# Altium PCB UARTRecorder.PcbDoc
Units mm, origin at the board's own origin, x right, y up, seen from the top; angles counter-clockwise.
Board outline 152.4 x 101.6 mm, 2 copper layers (Top Layer, Bottom Layer); 66 components, 53 nets, 258 pads, 164 vias.
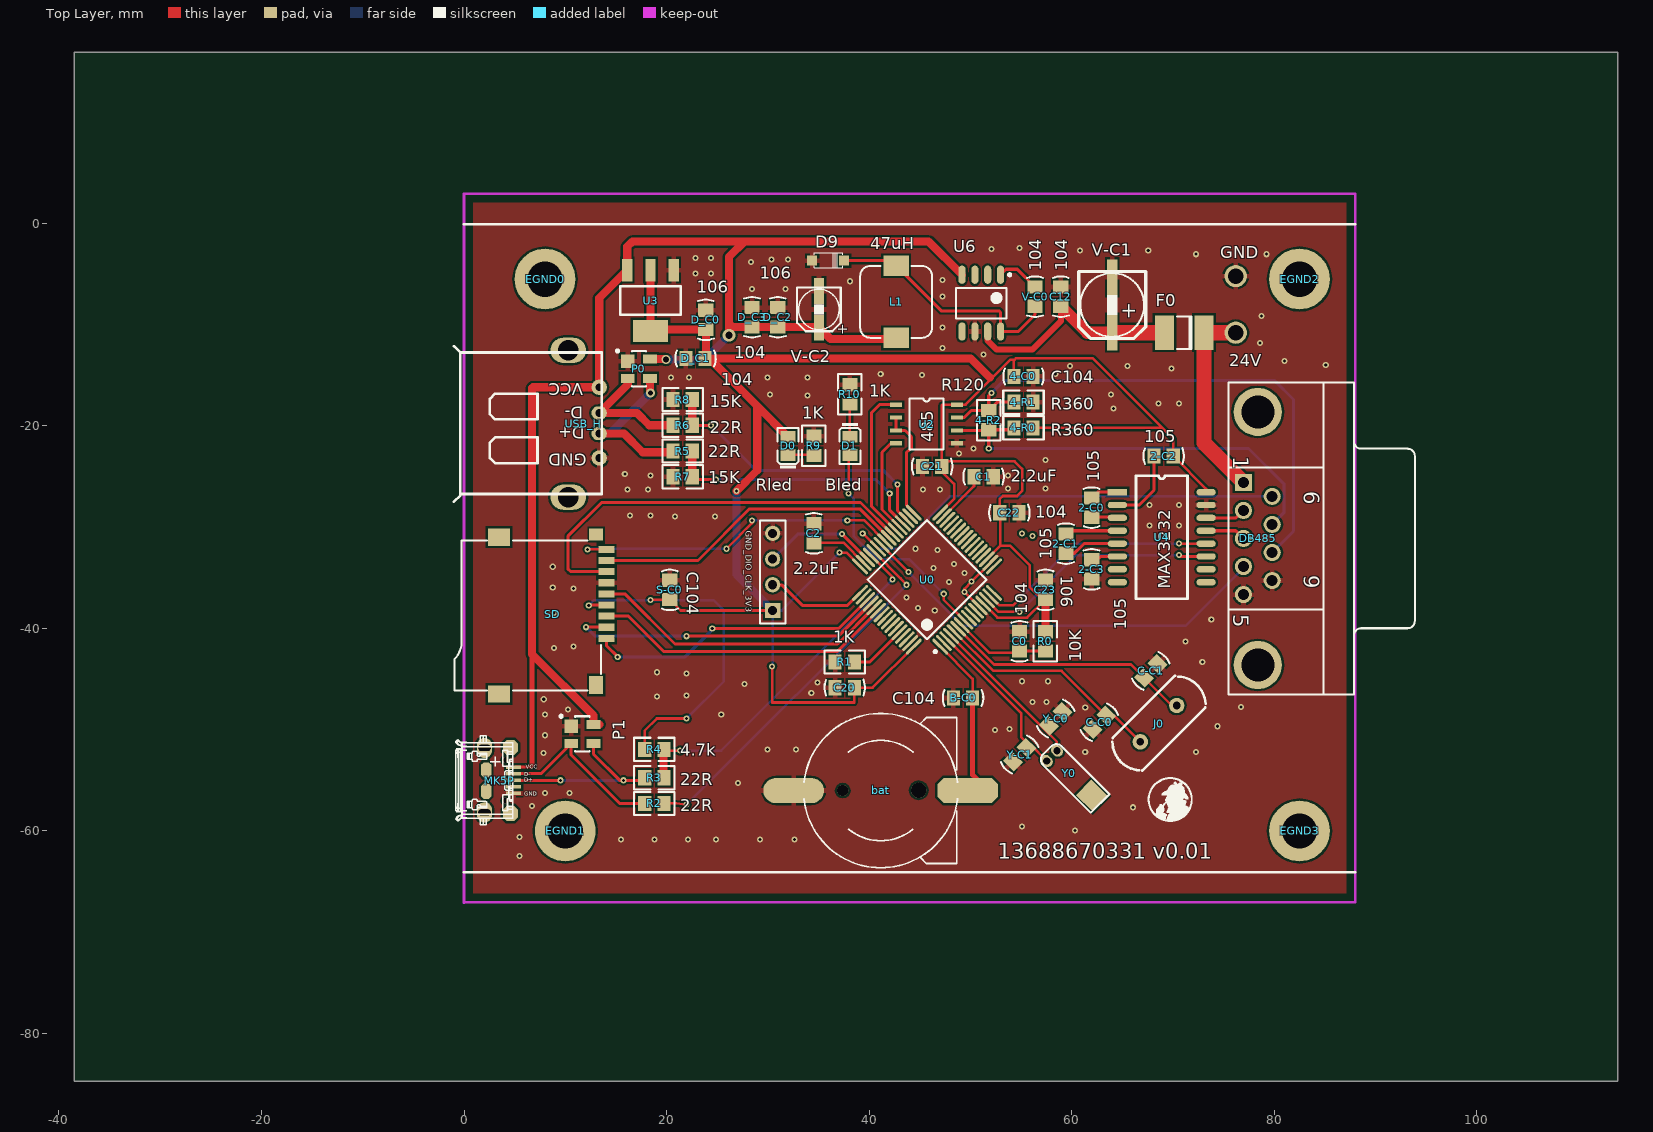
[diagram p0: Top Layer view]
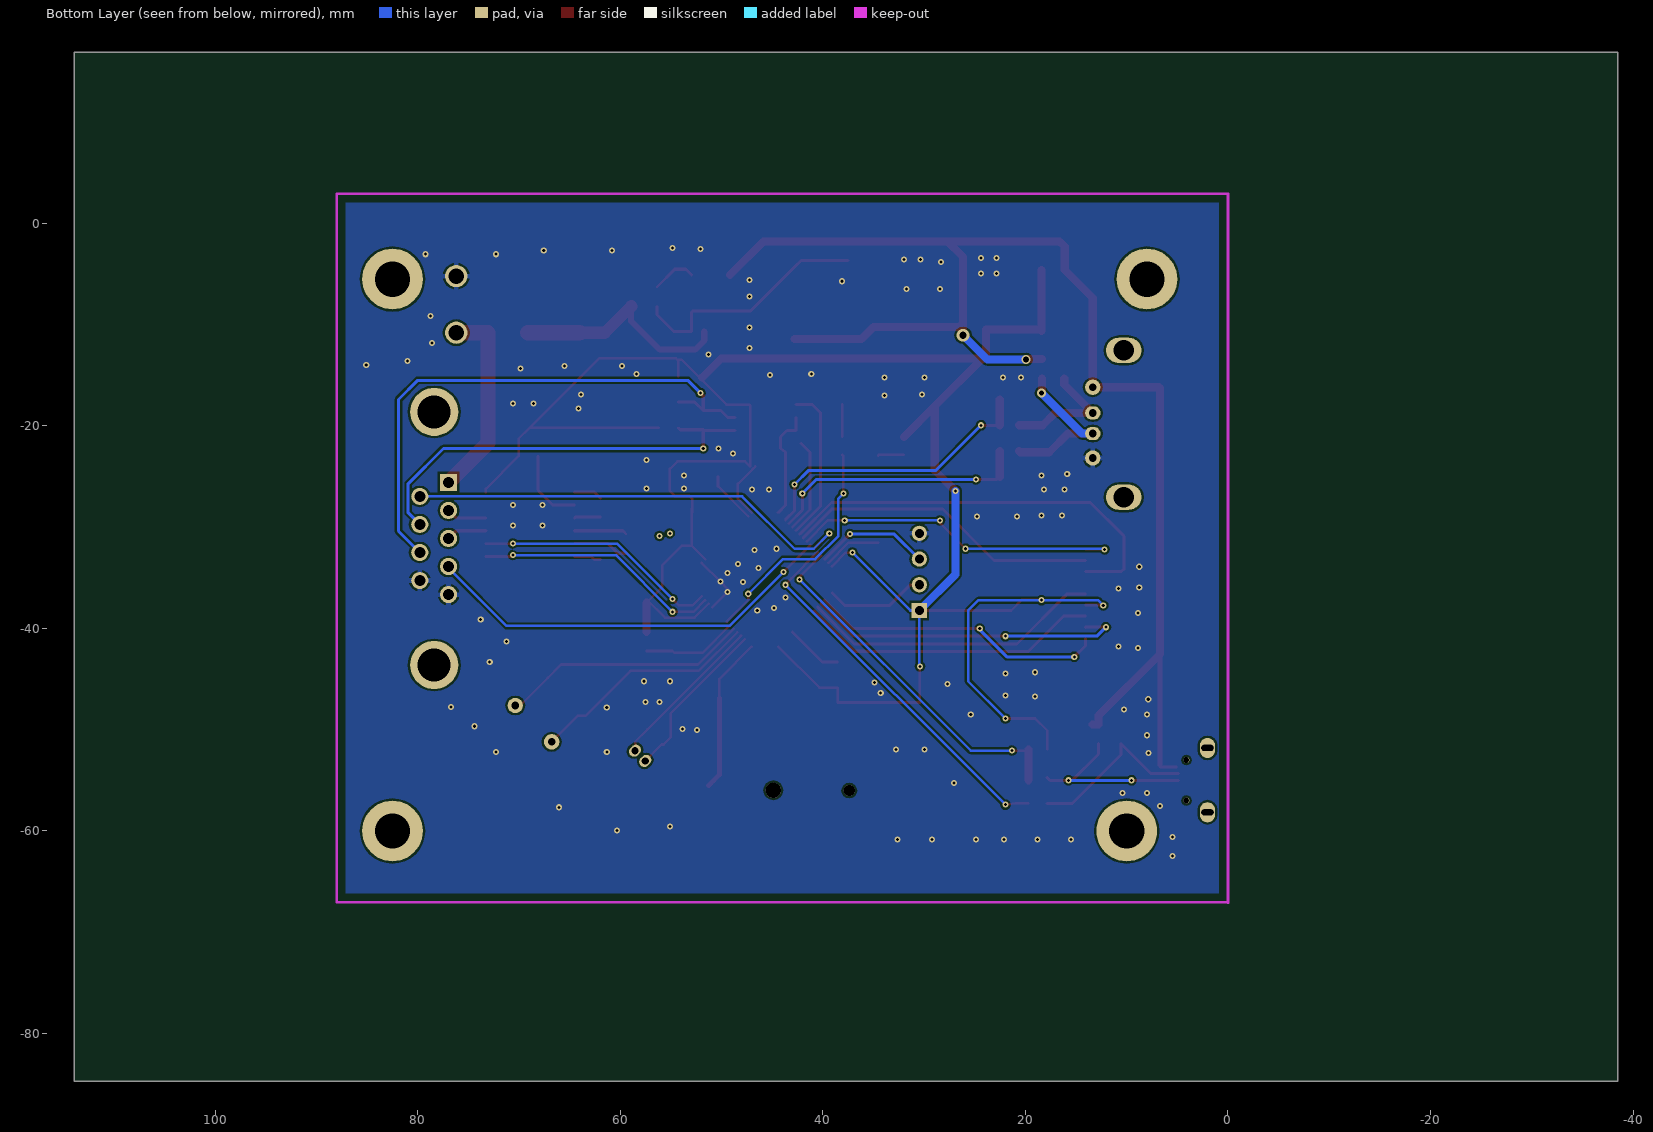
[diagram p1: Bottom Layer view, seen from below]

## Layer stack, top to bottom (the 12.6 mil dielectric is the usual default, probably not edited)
Top Layer: signal copper 0.0356
Dielectric: dielectric 0.32, FR-4, Dk 4.8
Bottom Layer: signal copper 0.0356

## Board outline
-38.481,-84.709 113.919,-84.709 113.919,16.891 -38.481,16.891

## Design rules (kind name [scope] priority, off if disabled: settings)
Clearance Clearance_keepout [(OnLayer('Keep-Out Layer'))] p1: gap=0.762
Clearance Clearance_ploy [inpoly] p2: gap=0.203
Clearance [All] p3: gap=0.152
ComponentClearance [All] p1: gap=0.127 collisioncheckmode=3 verticalgap=0.254 showdistances=FALSE
DiffPairsRouting DiffPair_DiffPairsRouting [InDifferentialPair ('VOUT2')] p1: maxlimit=0.254 minlimit=0.254 mostfreqgap=0.254 maxuncoupledlength=12.7
DiffPairsRouting [All] p2: maxlimit=0.254 minlimit=-0.044 mostfreqgap=0.254 toplayer_maxgap=-0.044 toplayer_prefgap=3.693 bottomlayer_maxgap=-0.044 bottomlayer_prefgap=2.348 maxuncoupledlength=12.7
HoleSize [All] p1: absolutevalues=TRUE maxlimit=5 minlimit=0.025 maxpercent=80.000 minpercent=20.000
HoleSize FabricationTestpoint [All] p2: absolutevalues=TRUE maxlimit=2.54 minlimit=0.025 maxpercent=80.000 minpercent=20.000
HoleSize FabricationTestPointUsage [All] p3: absolutevalues=TRUE maxlimit=2.54 minlimit=0.025 maxpercent=80.000 minpercent=20.000
Length [All] p1: maxlimit=152.4 minlimit=0
MatchedLengths DiffPair_MatchedLengths [InDifferentialPair ('VOUT2')] p1: tolerance=25.4 checknetsindiffpair=TRUE checkdiffpairvsdiffpair=TRUE checkothers=TRUE
MinimumSolderMaskSliver [All] p1: minsoldermaskwidth=0
MinimumSolderMaskSliver SilkToSolderMaskClearance [IsPad] p2: minsoldermaskwidth=0.254
NetAntennae AssemblyTestpoint [All] p1: netantennaetolerance=0
NetAntennae [All] p2: netantennaetolerance=0
NetAntennae AssemblyTestPointUsage [All] p3: netantennaetolerance=0
NetAntennae UnpouredPolygon [All] p4: netantennaetolerance=0
NetAntennae SilkToBoardRegionClearance [All] p5: netantennaetolerance=0
PlaneConnect [All] p1: planeconnectstyle=Direct reliefexpansion=0.508 reliefentries=4 reliefconductorwidth=0.254 reliefairgap=0.254
PolygonConnect PolygonConnect_VIA [ISVIA] p1: connectstyle=Direct reliefconductorwidth=0.254 reliefentries=4 polygonreliefangle="90 Angle"
PolygonConnect [All] p2: connectstyle=Relief reliefconductorwidth=0.508 reliefentries=4 polygonreliefangle="90 Angle"
RoutingVias [All] p1: holewidth=0.4 width=0.8 viastyle="Through Hole" minholewidth=0.3 minwidth=0.6 maxholewidth=1 maxwidth=2
SilkToSilkClearance [All] p1: silktosilkclearance=0
SilkscreenOverComponentPads [All] p1: minsilkscreentomaskgap=0.254
SolderMaskExpansion [All] p1: expansion=0.102
TestPointUsage [All] p1: valid=0 allowmultiple=FALSE
Testpoint [All] p1: side=15 testpointundercomponent=TRUE minsize=1.016 maxsize=2.54 preferedsize=1.524 minholesize=0 maxholesize=1.016 preferedholesize=0.813 testpointgrid=0.025 style=1023 order=0123456789
Width Width_VCC3.3 [InNet('G+3V3')] p1: maxlimit=2.54 minlimit=0.305 preferedwidth=0.305
Width DiffPair_Width [InDifferentialPair('VOUT2')] p2: maxlimit=0.254 minlimit=0.254 preferedwidth=0.254
Width [All] p3: maxlimit=2.54 minlimit=0.152 preferedwidth=0.203
16 further rules are at their usual default settings.

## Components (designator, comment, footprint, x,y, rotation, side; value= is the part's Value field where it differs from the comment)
2-C0 "105" C-RAD-0805 61.976,-28.067 r90 top
2-C1 "105" C-RAD-0805 59.436,-31.623 r90 top
2-C2 "105" C-RAD-0805 69.088,-22.987 r180 top
2-C3 "105" C-RAD-0805 61.976,-34.163 r90 top
4-C0 "C104" C-RAD-0805 55.245,-15.113 r180 top
4-R0 "R360" R2012-0805 55.245,-20.193 r180 top
4-R1 "R360" R2012-0805 55.245,-17.653 r180 top
4-R2 "R120" R2012-0805 51.816,-19.431 r90 top
24V "1孔" HOLEx1#1 76.2,-10.795 r0 top (schematic designator k0)
B-C0 "C104" C-RAD-0805 49.276,-46.863 r0 top
bat "Battery" BATM 41.148,-56.007 r90 top
C0 "104" C-RAD-0805 54.864,-41.275 r90 top
C1 "2.2uF" C-RAD-0805 51.308,-25.019 r0 top
C2 "2.2uF" C-RAD-0805 34.544,-30.607 r90 top
C12 "104" C-RAD-0805 58.928,-7.239 r90 top
C20 "104" C-RAD-0805 37.592,-45.847 r0 top
C21 "106" C-RAD-0805 46.228,-24.003 r0 top
C22 "104" C-RAD-0805 53.848,-28.575 r180 top
C23 "106" C-RAD-0805 57.404,-36.195 r270 top
C-C0 "22pF" C-RAD-0805 62.738,-49.276 r45 top
C-C1 "22pF" C-RAD-0805 67.818,-44.196 r225 top
D0 "Rled" 0805_LED_S1 32.004,-21.971 r90 top
D1 "Bled" 0805_LED_S1 38.1,-21.971 r270 top
D9 "S7" SOD123 36.576,-3.683 r0 top
D_C0 "106" C-RAD-0805 23.876,-9.525 r270 top
D_C1 "104" C-RAD-0805 22.86,-13.335 r0 top
D_C2 "106" C-RAD-0805 30.988,-9.271 r90 top
D_C3 "104" C-RAD-0805 28.448,-9.271 r90 top
DB485 "DB9母座" DB9-F 87.884,-31.115 r270 top locked
EGND0 "1孔" HOLEx1#2 5.588,-5.207 r90 top
EGND1 "1孔" HOLEx1#3 10.668,-59.436 r90 top
EGND2 "1孔" HOLEx1#4 81.788,6.096 r90 top
EGND3 "1孔" HOLEx1#5 76.708,-59.436 r90 top
F0 "Fuse 1" 1812 71.12,-10.795 r180 top
GND "1孔" HOLEx1#1 76.2,-5.207 r0 top (schematic designator k1)
GND_DIO_CLK_3V3 "Header 4" HDR1X4 30.48,-38.227 r90 top
J0 "25M" 晶振HC-49S 68.58,-49.403 r225 top
L1 "47uH" L-SMD-7 42.672,-7.747 r270 top
MK5P "五脚端子" USB-MICRO1 4.572,-54.991 r90 top
P0 "PRTR5V0U2X" SOT-143 17.272,-14.351 r270 top
P1 "PRTR5V0U2X" SOT-143 11.684,-50.419 r270 top
R0 "10K" R2012-0805 57.404,-41.275 r270 top
R1 "1K" R2012-0805 37.592,-43.307 r180 top
R2 "22R" R2012-0805 18.796,-57.277 r180 top
R3 "22R" R2012-0805 18.796,-54.737 r180 top
R4 "4.7k" R2012-0805 18.796,-51.943 r180 top
R5 "22R" R2012-0805 21.59,-22.479 r180 top
R6 "22R" R2012-0805 21.59,-19.939 r180 top
R7 "15K" R2012-0805 21.59,-25.019 r180 top
R8 "15K" R2012-0805 21.59,-17.399 r180 top
R9 "1K" R2012-0805 34.544,-21.971 r270 top
R10 "1K" R2012-0805 38.1,-16.891 r270 top
S-C0 "C104" C-RAD-0805 20.32,-36.195 r90 top
SD "microSD" SDCARD-M 3.048,-38.735 r180 top locked
U0 "STM32F205RBT6" LQFP-64 45.72,-35.179 r135 top
U2 "485" SOP8 42.672,-17.907 r0 top
U3 "AMS1117-3.3" SOT-223 18.415,-7.62 r90 top
U4 "MAX3232" SOP16-50-208 64.516,-26.543 r0 top
U6 "LM2675M-5.0" "SOP8 - 3d" 51.054,-7.874 r270 top
USB_H "五脚端子" USB 6.096,-19.939 r180 top locked
V-C0 "104" C-RAD-0805 56.388,-7.239 r270 top
V-C1 "100uF/37V" SMD-EC-F6.3 64.008,-10.795 r90 top
V-C2 "47uF/37v" SMD-EC-F4 35.052,-10.287 r90 top
Y0 "32.768M" XTAL32 58.547,-52.07 r315 top
Y-C0 "20pF" C-RAD-0805 58.42,-48.895 r225 top
Y-C1 "20pF" C-RAD-0805 54.864,-52.451 r45 top

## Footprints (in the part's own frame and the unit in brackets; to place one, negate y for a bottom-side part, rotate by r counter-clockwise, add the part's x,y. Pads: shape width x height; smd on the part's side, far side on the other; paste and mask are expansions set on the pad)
0805_LED_S1 [mm]
  rect 1.16x1.47 smd: A(0.89,0) K(-0.89,0)
  silkscreen extent -2.24,-1.04 1.77,1.03, body extent -1.01,-0.62 1.01,0.62, height 1.1
1812 [mm] "Chip Capacitor; Body 4.5 x 3.2 mm (LxW typ)"
  rect 1.9x3.4 smd: 1(-1.95,0) 2(1.95,0)
  silkscreen extent -0.7,-1.6 0.7,1.6
BATM [mm]
  round 1.1 hole 1.1 unplated: 0(0,3.748)
  round 1.5 hole 1.5 unplated: 0(0.025,-3.752)
  oct 2.5x6 smd: 1(0,-8.602)
  oval 2.5x6 smd: 2(0,8.598)
  silkscreen extent -7.62,-7.58 7.62,7.57
C-RAD-0805 [mm] "贴片电容"
  rect 1.3x1.5 smd: 1(-0.95,0) 2(0.95,0)
  silkscreen extent -2,-0.79 2,0.79, body extent -1.27,-0.64 1.27,0.64, height 0.9
DB9-F [mm] "DB9母座"
  rect 1.69x1.69 hole 1.09: 1(-5.54,-10.92)
  round 1.69 hole 1.09: 2(-2.77,-10.92) 3(0,-10.92) 4(2.77,-10.92) 5(5.54,-10.92) 6(-4.155,-8.08) 7(-1.385,-8.08) 8(1.385,-8.08) 9(4.155,-8.08)
  round 4.76 hole 3.26: 10(-12.495,-9.5) 11(12.495,-9.5)
  silkscreen extent -15.4,-12.4 15.4,6
HDR1X4 [mm] "Connector; Header; 4 Position"
  rect 1.5x1.5 hole 0.9: 1(0,0)
  round 1.5 hole 0.9: 2(2.54,0) 3(5.08,0) 4(7.62,0)
  silkscreen extent -1.27,-1.27 8.89,1.27
HOLEx1#1 [mm]
  round 2.2 hole 1.524: 1(0,0)
HOLEx1#2 [mm]
  round 6 hole 3.5 paste+0.15: 1(-0.293,-2.412)
HOLEx1#3 [mm]
  round 6 hole 3.5: 1(-0.564,0.668)
HOLEx1#4 [mm]
  round 6 hole 3.5: 1(-11.596,-0.712)
HOLEx1#5 [mm]
  round 6 hole 3.5: 1(-0.564,-5.792)
L-SMD-7 [mm] "贴片电感7*7"
  rect 2x2.5 smd: 1(-3.556,0) 2(3.556,0)
  silkscreen extent -3.56,-3.56 3.56,3.56, body extent -3.56,-3.56 3.56,3.56, height 4
LQFP-64 [mm] "LQFP64"
  oval 2.1x0.3 smd: 1(-5.6,3.75) 2(-5.6,3.25) 3(-5.6,2.75) 4(-5.6,2.25) 5(-5.6,1.75) 6(-5.6,1.25) 7(-5.6,0.75) 8(-5.6,0.25) 9(-5.6,-0.25) 10(-5.6,-0.75) 11(-5.6,-1.25) 12(-5.6,-1.75) 13(-5.6,-2.25) 14(-5.6,-2.75) 15(-5.6,-3.25) 16(-5.6,-3.75) 33(5.6,-3.75) 34(5.6,-3.25) 35(5.6,-2.75) 36(5.6,-2.25) 37(5.6,-1.75) 38(5.6,-1.25) 39(5.6,-0.75) 40(5.6,-0.25) 41(5.6,0.25) 42(5.6,0.75) 43(5.6,1.25) 44(5.6,1.75) 45(5.6,2.25) 46(5.6,2.75) 47(5.6,3.25) 48(5.6,3.75)
  oval 0.3x2.1 smd: 17(-3.75,-5.6) 18(-3.25,-5.6) 19(-2.75,-5.6) 20(-2.25,-5.6) 21(-1.75,-5.6) 22(-1.25,-5.6) 23(-0.75,-5.6) 24(-0.25,-5.6) 25(0.25,-5.6) 26(0.75,-5.6) 27(1.25,-5.6) 28(1.75,-5.6) 29(2.25,-5.6) 30(2.75,-5.6) 31(3.25,-5.6) 32(3.75,-5.6) 49(3.75,5.6) 50(3.25,5.6) 51(2.75,5.6) 52(2.25,5.6) 53(1.75,5.6) 54(1.25,5.6) 55(0.75,5.6) 56(0.25,5.6) 57(-0.25,5.6) 58(-0.75,5.6) 59(-1.25,5.6) 60(-1.75,5.6) 61(-2.25,5.6) 62(-2.75,5.6) 63(-3.25,5.6) 64(-3.75,5.6)
  silkscreen extent -5.72,-4.15 4.15,4.57, body extent -5,-5 5,5, height 1.6
R2012-0805 [mm] "Thermistor; 2 Leads"
  rect 1.3x1.5 smd: 1(-0.95,0) 2(0.95,0)
  silkscreen extent -2,-1.15 2,1.15, body extent -1.02,-0.64 0.98,0.62
SDCARD-M [mm] "TF卡"
  rect 1.6x0.7 smd: 1(-11.008,2.25) 2(-11.008,1.15) 3(-11.008,0.05) 4(-11.008,-1.05) 5(-11.008,-2.15) 6(-11.008,-3.25) 7(-11.008,-4.35) 8(-11.008,-5.45) 9(-11.008,-6.55)
  rect 1.4x1.2 smd: 10(-10,-8.004)
  rect 2.2x1.7 smd: 11(-0.4,-7.75) 13(-0.4,7.75)
  rect 1.4x1.8 smd: 12(-10,6.85)
  silkscreen extent -10.5,-7.4 4,7.4
SMD-EC-F4 [mm]
  rect 2.6x1 smd: 1(0,0) 2(3.579,0)
  silkscreen extent -0.36,-2.15 3.94,2.15
SMD-EC-F6.3 [mm]
  rect 3.5x1 smd: 1(0,0) 2(5.475,0)
  silkscreen extent -0.56,-3.31 6.04,3.31
SOD123 [mm] "Chip Capacitor; Body 2.0 x 1.2 mm (LxW typ)"
  rect 1x1 smd: 1(-2.2,0) 2(0.95,0)
  silkscreen extent -2,-0.7 0.8,0.8
SOP8 [mm]
  rect 1.2x0.42 smd: 1(0,0) 2(0,-1.27) 3(0,-2.54) 4(0,-3.81) 5(6,-3.81) 6(6,-2.54) 7(6,-1.27) 8(6,0)
  silkscreen extent 1.33,-4.44 4.67,0.64
"SOP8 - 3d" [mm]
  oval 1.8x0.7 smd: 1(-2.8,1.93) 2(-2.8,0.66) 3(-2.8,-0.61) 4(-2.8,-1.88) 5(2.8,-1.88) 6(2.8,-0.61) 7(2.8,0.66) 8(2.8,1.93)
  silkscreen extent -2.92,-2.48 1.5,2.96, body extent -3.02,-2.51 3.02,2.51, height 1.6
SOP16-50-208 [mil]
  rect 75x25 smd: 1(0,0)
  oval 75x25 smd: 2(0,-50) 3(0,-100) 4(0,-150) 5(0,-200) 6(0,-250) 7(0,-300) 8(0,-350) 9(345,-350) 10(345,-300) 11(345,-250) 12(345,-200) 13(345,-150) 14(345,-100) 15(345,-50) 16(345,0)
  silkscreen extent 72,-414 272,64
SOT-143 [mm] "SOT-143; 4 Leads; Body 3 x 2.6 mm, inc. leads (LxW max)"
  rect 1.35x1.35 smd: 1(-0.75,-1.1)
  rect 0.9x1.35 smd: 2(0.95,-1.1) 3(0.95,1.1) 4(-0.95,1.1)
  silkscreen extent -1.87,-2.22 1.75,0.7
SOT-223 [mm]
  rect 2.2x1 smd: 1(3,-2.3) 2(3,0) 3(3,2.3)
  rect 2.2x3.5 smd: 2(-3,0)
  silkscreen extent -1.4,-3 1.4,3, body extent -3.49,-3.24 3.49,3.24, height 1.64
USB [mm]
  round 1.524 hole 0.762: 1(-7.255,-3.757) 4(-7.255,3.228)
  oval 1.524x1.324 hole 0.762: 2(-7.255,-1.217) 3(-7.255,0.815)
  oval 3.5x2.5 hole 2: VSS(-4.2,7.1) VSS2(-4.2,-7.4)
  silkscreen extent -7.51,-7.82 7.1,7.55, body extent -8,-8.1 6.1,7.7, height 6.35
USB-MICRO1 [mm] "USB AF/10.0 4P母座卷边SMT(前插后贴) H=6.8mm"
  rect 0.35x1.5 smd: 1(-1.3,-0.33) 2(-0.65,-0.33) 3(0,-0.33) 4(0.65,-0.33) 5(1.3,-0.33)
  oct 1.5x1.5 smd: ""(-3.275,-0.025) ""(3.225,-0.025)
  oval 2x1.5 hole 0.6 slot 1.2 at 90 deg: ""(-3.165,2.545) ""(3.195,2.545)
  oct 1.5x1 smd: ""(-1.075,2.375) ""(1.025,2.375)
  silkscreen extent -4.41,-0.23 4.4,5.39
XTAL32 [mil]
  oval 50x40 hole 28: 1(0,0) 2(0,-56)
  rect 92.13x86 smd: ""(220,-27)
  silkscreen extent -28,-77 264,25
晶振HC-49S [mil]
  round 60 hole 30: 1(100,0) 2(-100,0)
  silkscreen extent -212,-87 209,84, body extent -223,-93 223,90, height 138

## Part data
2-C0 2-C1 2-C2 2-C3: library part "0805 1uF (105) 10% 50V", "贴片电容"
4-C0 B-C0 S-C0: library part "Cap Semi", "Capacitor (Semiconductor SIM Model)"
4-R0 4-R1 4-R2: library part Res3, "Resistor"
bat: "Multicell Battery"
C0 D_C0 D_C1 D_C2 D_C3 V-C0: library part "0805 100nF(104) 10% 50V", "贴片电容"
C1 C2: library part "0805 2.2uF (225) 20% 50V", "贴片电容"
C12 C20 C21 C22 C23: library part Cap, "Capacitor"
C-C0 C-C1: library part "0603 22pF (220) 5% 50V", "贴片电容"
D0: library part "0805 红灯", "发光二极管"
D1: library part "0805 蓝灯", "发光二极管"
D9: library part "D Schottky", "Schottky Diode"
DB485: library part 9脚封装DB9
F0: "Fuse"
GND_DIO_CLK_3V3: "Header, 4-Pin"
J0: library part 晶振
L1: library part Lnductor
R0 R2 R3 R4 R5 R6 R7 R8 R9 R10: library part "0805 1KΩ (1001) 1%", "贴片电阻"
R1: library part "0603 1KΩ (1001) 1%", "贴片电阻"
U0: "ARM Cortex-M3 32-bit MCU, 128 KB Flash, 64 KB Internal RAM, 51 I/Os, 64-pin LQFP, -40 to 85 degC, Tray"
U2: library part SP3485
U3: library part "SOT-223 AMS1117-3.3", "低压差线性稳压(LDO)"
U6: library part TPS5410
V-C1 V-C2: library part "Cap Pol3", "Polarized Capacitor (Surface Mount)"
Y0: library part XTAL, "Crystal Oscillator"
Y-C0 Y-C1: library part "0805 20pF (200) 5% 50V", "贴片电容"

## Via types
v1: diameter 0.6, hole 0.3, Top Layer to Bottom Layer, 159 vias
v2: diameter 0.6, hole 0.55, Top Layer to Bottom Layer, 2 vias
v3: diameter 1.27, hole 0.711, Top Layer to Bottom Layer, 1 vias
v4: diameter 0.9, hole 0.5, Top Layer to Bottom Layer, 1 vias
v5: diameter 0.9, hole 0.6, Top Layer to Bottom Layer, 1 vias

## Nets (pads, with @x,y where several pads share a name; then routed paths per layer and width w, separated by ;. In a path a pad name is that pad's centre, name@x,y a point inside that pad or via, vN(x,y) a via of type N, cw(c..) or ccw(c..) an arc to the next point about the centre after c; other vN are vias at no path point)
BAT: B-C0.2 bat.1 U0.1 | length 15.5
  Top Layer w0.254: U0.1 50.226,-44.988 B-C0.2
  Top Layer w0.5: B-C0.2 50.226,-54.451 50.766,-54.991 bat.1@51.274,-55.499
GND: 2-C3.1 4-C0.1 4-R1.1 B-C0.1 bat.2 C0.2 C1.2 C2.2 C12.2 C20.1 C21.1 C22.1 C23.1 C-C0.1 C-C1.1 D9.1 D_C0.1 D_C1.1 D_C2.2 D_C3.2 DB485.5 DB485.9 GND.1 GND_DIO_CLK_3V3.4 MK5P.1 P0.1 P1.1 R1.2 R7.2 R8.2 R9.1 R10.1 S-C0.2 SD.6 U0.12 U0.18 U0.63 U2.5 U3.1 U4.15 U6.6 USB_H.4 V-C1.2 V-C2.2 Y-C0.1 Y-C1.1 | length 6.1
  Top Layer w0.254: U0.12 v1(49.403,-36.387) 49.403,-36.092 v1(50.126,-35.369) U0.18
  other v1: 5.461,-62.484 15.494,-60.833 18.796,-60.833 22.098,-60.833 24.892,-60.833 29.21,-60.833 32.639,-60.833 5.461,-60.579 60.325,-59.944 55.118,-59.563 66.04,-57.658 6.731,-57.531 8.001,-56.261 10.414,-56.261 27.051,-55.245 7.87,-52.305 61.341,-52.197 72.263,-52.197 29.972,-51.943 32.766,-51.943 8.001,-50.546 52.451,-50.038 53.848,-49.911 74.422,-49.657 8.001,-48.514 25.4,-48.514 10.287,-48.006 61.343,-47.808 76.708,-47.752 56.134,-47.244 57.531,-47.244 7.874,-46.99 19.05,-46.736 21.971,-46.609 34.29,-46.355 27.686,-45.466 34.925,-45.339 55.118,-45.212 57.658,-45.212 21.971,-44.45 19.05,-44.323 72.898,-43.307 8.89,-41.91 10.795,-41.783 71.247,-41.275 73.787,-39.116 8.89,-38.481 46.482,-38.227 44.831,-37.973 43.688,-36.957 10.795,-36.068 8.763,-35.941 47.879,-35.433 49.403,-34.544 46.355,-34.036 8.763,-33.909 48.387,-33.655 46.736,-32.258 44.577,-32.131 67.691,-29.845 70.612,-29.845 20.828,-28.956 24.765,-28.956 16.383,-28.829 18.415,-28.829 67.691,-27.813 70.612,-27.813 16.129,-26.289 18.161,-26.289 45.339,-26.289 46.99,-26.289 53.721,-26.162 57.404,-26.162 18.415,-24.892 53.721,-24.892 15.875,-24.765 57.404,-23.368 48.895,-22.733 50.292,-22.225 64.135,-18.288 68.58,-17.78 70.612,-17.78 33.909,-17.018 30.226,-16.891 63.881,-16.891 20.447,-15.24 22.225,-15.24 29.972,-15.24 33.909,-15.24 45.212,-14.986 41.148,-14.859 58.42,-14.859 69.85,-14.351 59.817,-14.097 65.532,-14.097 85.09,-13.97 81.026,-13.589 51.308,-12.954 47.244,-12.319 78.613,-11.811 47.244,-10.287 78.74,-9.144 47.244,-7.239 28.448,-6.477 31.75,-6.477 38.1,-5.715 47.244,-5.588 22.86,-4.953 24.384,-4.953 28.321,-3.81 30.353,-3.556 32.004,-3.556 22.86,-3.429 24.384,-3.429 72.263,-3.048 79.248,-3.048 60.833,-2.667 67.564,-2.667 52.07,-2.54 54.864,-2.413
IO2: P0.2 R6.2 USB_H.2 | length 12.4
  Top Layer w0.8: P0.2 16.172,-15.901 USB_H.2 17.071,-18.722 18.288,-19.939 R6.2
IO3: P0.3 R5.2 USB_H.3 | length 16.3
  Top Layer w0.8: USB_H.3 15.801,-20.754 17.653,-22.606 20.513,-22.606 R5.2 ; P0.3 18.372,-16.721 v4(18.415,-16.764)
  Bottom Layer w0.8: USB_H.3 14.425,-20.754 v4(18.415,-16.764)
IO4: MK5P.4 P1.2 R2.2 | length 17.3
  Top Layer w0.3: MK5P.4 7.612,-54.341 P1.2 10.584,-52.494 15.367,-57.277 R2.2
IO5: MK5P.3 P1.3 R3.2 | length 18.1
  Top Layer w0.3: MK5P.3 v1(9.525,-54.991) ; P1.3 12.784,-52.408 15.367,-54.991 v1(15.748,-54.991) 17.592,-54.991 R3.2
  Bottom Layer w0.3: v1(9.525,-54.991) v1(15.748,-54.991)
LED: D1.A U0.8 | length 23.1
  Top Layer w0.254: v1(37.973,-26.67) 37.973,-22.988 D1.A ; v1(47.371,-36.576) 47.371,-37.184 U0.8
  Bottom Layer w0.254: v1(37.973,-26.67) 38.481,-27.178 38.481,-30.861 40.767,-33.147 43.942,-33.147 v1(47.371,-36.576)
Net2-C0_1: 2-C0.1 U4.3 | length 2.6
  Top Layer w0.3: 2-C0.1 64.45,-29.017 U4.3
Net2-C0_2: 2-C0.2 U4.1 | length 2.8
  Top Layer w0.3: 2-C0.2 62.55,-26.543 U4.1
Net2-C1_1: 2-C1.1 U4.5 | length 5.5
  Top Layer w0.3: 2-C1.1 60.264,-32.573 61.214,-31.623 U4.5
Net2-C1_2: 2-C1.2 U4.4 | length 5.2
  Top Layer w0.3: 2-C1.2 59.756,-30.353 U4.4
Net2-C2_2: 2-C2.2 U4.2 | length 7.6
  Top Layer w0.3: U4.2 66.675,-27.813 68.138,-26.35 2-C2.2
Net2-C3_2: 2-C3.2 U4.6 | length 2.7
  Top Layer w0.3: 2-C3.2 62.545,-33.213 62.865,-32.893 U4.6
NetC1_1: C1.1 U0.31 | length 5.1
  Top Layer w0.254: U0.31 50.358,-25.945 C1.1
NetC2_1: C2.1 U0.47 | length 5.7
  Top Layer w0.254: C2.1 37.502,-31.557 U0.47
NetD0_K: D0.K R9.2 | length 2.6
  Top Layer w0.254: D0.K 34.484,-22.861 R9.2
NetD1_K: D1.K R10.2 | length 3.2
  Top Layer w0.254: D1.K R10.2
NetD9_2: D9.2 L1.1 U6.8 V-C0.2 | length 24.4
  Top Layer w0.3: D9.2 42.164,-3.683 L1.1 47.117,-8.636 52.832,-8.636 52.984,-8.788 U6.8 54.731,-10.674 56.388,-9.017 V-C0.2
NetR1_1: R1.1 U0.60 | length 5.7
  Top Layer w0.3: R1.1 40.067,-43.307 U0.60
NetU6_1: U6.1 V-C0.1 | length 4.4
  Top Layer w0.3: U6.1 53.525,-4.533 54.632,-4.533 V-C0.1
NRST: C0.1 R0.2 U0.7 | length 9.5
  Top Layer w0.254: U0.7 51.898,-42.418 54.671,-42.418 C0.1 R0.2
OSC32_IN: U0.3 Y0.2 Y-C1.2 | length 16.2
  Top Layer w0.254: U0.3 55.028,-48.376 55.028,-50.763 55.726,-51.462 55.927,-51.462 Y0.2
OSC32_OUT: U0.4 Y0.1 Y-C0.2 | length 15.7
  Top Layer w0.254: U0.4 57.337,-49.978 58.547,-51.188 Y0.1
OSC_IN: C-C0.2 J0.1 U0.5 | length 22.8
  Top Layer w0.254: U0.5 52.262,-44.196 59.002,-44.196 C-C0.2 64.189,-48.604 J0.1
OSC_OUT: C-C1.2 J0.2 U0.6 | length 24.7
  Top Layer w0.254: U0.6 52.334,-43.561 65.839,-43.561 C-C1.2 69.885,-47.607 J0.2
RS232_RX: DB485.3 U4.13 | length 4
  Top Layer w0.3: U4.13 76.202,-30.353 DB485.3
RS232_TX: DB485.2 U4.14 | length 4
  Top Layer w0.3: U4.14 76.226,-29.083 DB485.2
RS485_A: 4-R0.2 4-R2.1 DB485.7 U2.6 | length 42.6
  Top Layer w0.3: U2.6 51.75,-20.447 4-R2.1 ; v1(51.816,-22.225) 4-R2.1 ; 4-R0.2 54.107,-20.381 4-R2.1
  Bottom Layer w0.3: v1(51.816,-22.225) 77.47,-22.225 80.953,-25.708 80.953,-28.581 DB485.7
RS485_B: 4-R1.2 4-R2.2 DB485.8 U2.7 | length 55.2
  Top Layer w0.3: U2.7 49.403,-19.177 50.099,-18.481 4-R2.2 ; v1(52.07,-16.764) 51.816,-17.018 4-R2.2 ; 4-R1.2 52.644,-17.653 4-R2.2
  Bottom Layer w0.3: v1(52.07,-16.764) 53.34,-15.494 80.01,-15.494 81.915,-17.399 81.915,-30.389 DB485.8
RS485_RE: U0.33 U2.2 U2.3 | length 11.1
  Top Layer w0.3: U2.2 U2.3 43.561,-20.447 44.196,-21.082 44.196,-22.225 43.688,-22.606 43.688,-27.844 U0.33
SD_CK: SD.5 U0.53 | length 30
  Top Layer w0.3: SD.5 15.884,-36.585 20.828,-41.529 36.895,-41.529 U0.53
SD_CMD: SD.3 U0.54 | length 29.9
  Top Layer w0.3: SD.3 16.245,-38.785 19.751,-42.291 35.828,-42.291 35.866,-42.253 36.878,-42.253 U0.54
SD_D0: SD.7 U0.39 | length 41.8
  Top Layer w0.3: SD.7 10.509,-34.385 10.287,-34.163 10.287,-30.861 13.589,-27.559 39.161,-27.559 U0.39
SD_D1: SD.8 U0.40 | length 31.5
  Top Layer w0.3: SD.8 15.494,-33.285 ; 15.748,-33.274 15.505,-33.274 15.494,-33.285 ; U0.40@41.96,-31.065 U0.40 39.089,-28.194 28.194,-28.194 23.103,-33.285 15.494,-33.285
SD_D2: SD.1 U0.51 | length 29.3
  Top Layer w0.3: SD.1 14.056,-41.676 v1(15.179,-42.799) ; v1(24.511,-40.005) 37.005,-40.005 U0.51
  Bottom Layer w0.3: v1(15.179,-42.799) 21.844,-42.799 24.511,-40.132 v1(24.511,-40.005)
SD_D3: SD.2 U0.52 | length 31.8
  Top Layer w0.3: v1(12.065,-39.878) 14.049,-39.878 SD.2 ; v1(21.971,-40.767) 36.95,-40.767 U0.52
  Bottom Layer w0.3: v1(12.065,-39.878) 12.954,-40.767 v1(21.971,-40.767)
SD_EXTI: SD.9 U0.41 | length 33.6
  Top Layer w0.254: v1(12.192,-32.185) SD.9 ; v1(25.908,-32.131) 28.448,-29.591 v1(28.448,-29.337) ; v1(37.846,-29.337) 39.524,-29.337 U0.41
  Bottom Layer w0.254: v1(12.192,-32.185) 12.246,-32.131 v1(25.908,-32.131) v1@26.035,-32.004 ; v1(28.448,-29.337) v1(37.846,-29.337)
SW_CLK: GND_DIO_CLK_3V3.2 U0.49 | length 10
  Top Layer w0.3: GND_DIO_CLK_3V3.2 31.369,-35.687 33.401,-37.719 37.877,-37.719 U0.49
SWDIO: GND_DIO_CLK_3V3.3 U0.46 | length 11.4
  Top Layer w0.3: v1(37.338,-30.686) U0.46
  Bottom Layer w0.3: GND_DIO_CLK_3V3.3 32.941,-30.686 v1(37.338,-30.686)
UART1_RX: DB485.6 U0.43 | length 45.2
  Top Layer w0.254: v1(39.37,-30.607) 39.38,-30.607 U0.43
  Bottom Layer w0.254: v1@39.439,-30.665 40.904,-32.131 42.799,-32.131 47.97,-26.96 DB485.6
UART1_TX: DB485.4 U0.42 | length 41.6
  Top Layer w0.254: U0.42 v1(43.897,-34.417)
  Bottom Layer w0.254: v1(43.897,-34.417) 49.231,-39.751 71.247,-39.751 76.964,-34.034 DB485.4
UART4_RX: U0.15 U4.12 | length 24.2
  Top Layer w0.254: U0.15 52.856,-37.719 54.229,-37.719 v1(54.864,-37.084) ; v1(70.612,-31.623) U4.12
  Bottom Layer w0.254: v1(54.864,-37.084) 60.325,-31.623 v1(70.612,-31.623)
UART4_TX: U0.14 U4.11 | length 24.5
  Top Layer w0.254: U0.14 52.784,-38.354 v1(54.864,-38.354) ; v1(70.612,-32.766) 70.739,-32.893 U4.11
  Bottom Layer w0.254: v1(54.864,-38.354) 60.452,-32.766 v1(70.612,-32.766)
UART6_RX: U0.38 U2.1 | length 15.4
  Top Layer w0.3: U0.38 40.259,-27.95 40.259,-18.669 41.021,-17.907 U2.1
UART6_TX: U0.37 U2.4 | length 9.3
  Top Layer w0.3: U2.4@42.164,-21.717 41.275,-22.606 41.275,-28.259 U0.37
USB_D+: R3.1 R4.1 U0.45 | length 35.9
  Top Layer w0.254: R4.1 19.873,-52.07 v1(21.336,-52.07) ; U0.45 42.291,-34.932 v1(42.291,-35.179)
  Top Layer w0.8: R3.1@19.685,-54.991 19.685,-54.737 R4.1@19.685,-51.943
  Bottom Layer w0.254: v1(21.336,-52.07) 25.4,-52.07 v1(42.291,-35.179)
USB_D-: R2.1 U0.44 | length 37.5
  Top Layer w0.254: R2.1 20.955,-57.277 v1(21.971,-57.404) ; U0.44 43.118,-35.052 v1(43.688,-35.687)
  Bottom Layer w0.254: v1(21.971,-57.404) v1(43.688,-35.687)
USB_HD+: R5.1 R7.1 U0.36 | length 25.9
  Top Layer w0.3: R7.1@22.794,-25.273 v1(24.892,-25.273) ; v1(42.037,-26.67) 42.037,-28.314 U0.36
  Top Layer w0.8: R7.1 R5.1
  Bottom Layer w0.3: v1(24.892,-25.273) 40.64,-25.273 v1(42.037,-26.67)
USB_HD-: R6.1 R8.1 U0.35 | length 29.1
  Top Layer w0.3: R6.1 v1(24.384,-19.939) ; v1(42.799,-25.781) 42.799,-28.369 U0.35
  Top Layer w0.8: R6.1 R8.1
  Bottom Layer w0.3: v1(24.384,-19.939) 28.829,-24.384 41.402,-24.384 v1(42.799,-25.781)
VCC-24V: 24V.1 DB485.1 F0.1 | length 19.5
  Top Layer w1.5: 24V.1 F0.1 73.07,-21.681 DB485.1
VCC_3.3V: 2-C2.1 4-C0.2 4-R0.1 C20.2 C21.2 C22.2 C23.2 D0.A D_C0.2 D_C1.2 GND_DIO_CLK_3V3.1 R0.1 R4.2 S-C0.1 SD.4 U0.13 U0.19 U0.32 U0.48 U0.64 U2.8 U3.2 U4.16 | length 260.9
  Top Layer w0.254: v1(12.319,-37.719) 12.353,-37.685 SD.4 ; R4.2 17.846,-50.099 19.05,-48.895 v1(21.971,-48.895) ; v1(18.415,-37.211) 18.481,-37.145 S-C0.1 21.402,-38.227 GND_DIO_CLK_3V3.1 ; v1(30.419,-43.749) 30.419,-47.31 38.542,-47.31 C20.2 40.355,-45.847 U0.64 ; v1(37.084,-32.512) 37.75,-32.512 U0.48 ; C21.2@46.67,-24.003 46.924,-24.257 48.387,-25.72 48.387,-27.209 U0.32 ; U0.13 52.658,-38.935 55.614,-38.935 C23.2@57.244,-37.305 ; U0.19 52.959,-31.829 ; C22.2 52.898,-27.239 53.213,-26.924 54.61,-26.924 55.118,-26.416 55.118,-24.257 54.356,-23.495 47.686,-23.495 C21.2 47.178,-17.968 47.239,-17.907 U2.8 49.53,-17.907 53.975,-13.462 54.356,-13.462 ; C22.2@52.959,-28.194 52.959,-28.575 52.959,-31.829 ; 4-C0.2 54.295,-13.523 54.356,-13.462 ; 4-R0.1 68.961,-20.193 ; C23.2@57.404,-37.465 C23.2@57.244,-37.305 ; C23.2 C23.2@57.244,-37.305 ; U4.16 73.279,-26.228 2-C2.1 70.038,-21.27 68.961,-20.193 ; 52.959,-31.829 53.927,-31.829 55.88,-33.782 55.88,-35.941 C23.2@57.244,-37.305 ; 54.356,-13.462 54.483,-13.335 62.103,-13.335 68.961,-20.193
  Top Layer w0.8: U3.2@18.415,-4.62 18.415,-10.62 18.56,-10.475 D_C0.2 23.876,-13.269 D_C1.2 D_C1.2@24.258,-13.335 ; v1(26.924,-26.416) 28.957,-24.383 28.957,-18.034 ; D0.A 28.957,-18.034 ; 51.943,-15.24 50.038,-13.335 D_C1.2@24.258,-13.335 ; R0.1 C23.2@57.404,-37.465 ; D_C1.2@24.258,-13.335 28.957,-18.034
  Bottom Layer w0.254: v1(12.319,-37.719) 12.827,-37.211 v1(18.415,-37.211) 24.638,-37.211 25.654,-38.227 25.654,-45.212 v1(21.971,-48.895) ; v1(30.419,-43.749) 30.48,-43.688 GND_DIO_CLK_3V3.1 31.369,-38.227 v1(37.084,-32.512)
  Bottom Layer w0.8: v1(26.924,-26.416) 26.924,-34.671 GND_DIO_CLK_3V3.1
VCC_5V: D_C2.1 D_C3.1 L1.2 MK5P.5 P0.4 P1.4 U3.3 U6.4 USB_H.1 V-C2.1 | length 141.6
  Top Layer w0.3: MK5P.5@5.08,-53.691 6.731,-53.691
  Top Layer w0.5: 6.731,-53.467 6.731,-42.545 6.731,-42.164
  Top Layer w0.8: P1.4@13.396,-49.469 P1.4 12.784,-48.598 6.731,-42.545 6.731,-16.256 6.805,-16.182 USB_H.1 13.351,-7.384 U3.3 16.115,-2.3 16.637,-1.778 27.686,-1.778 ; P0.4 v5@19.939,-13.401 ; v3(26.162,-11.049) 26.162,-9.906 ; L1.2@42.799,-11.43 42.672,-11.43 36.195,-11.43 V-C2.1 34.986,-10.221 D_C2.1 D_C3.1 26.477,-10.221 26.162,-9.906 ; U6.4 45.878,-1.778 27.686,-1.778 ; 26.162,-9.906 26.162,-3.302 27.686,-1.778
  Bottom Layer w0.8: v5(19.939,-13.462) 23.749,-13.462 v3(26.162,-11.049)
VIN: C12.1 F0.2 U6.7 V-C1.1 | length 22.4
  Top Layer w0.6: U6.7 51.714,-11.582 52.603,-12.471 56.109,-12.471 58.928,-9.652 C12.1
  Top Layer w1.2: C12.1 61.534,-10.795 V-C1.1
  Top Layer w1.5: V-C1.1 F0.2
pads on no net: bat.0 DB485.10 DB485.11 EGND0.1 EGND1.1 EGND2.1 EGND3.1 MK5P. MK5P.2 SD.10 SD.11 SD.12 SD.13 U0.2 U0.9 U0.10 U0.11 U0.16 U0.17 U0.20 U0.21 U0.22 U0.23 U0.24 U0.25 U0.26 U0.27 U0.28 U0.29 U0.30 U0.34 U0.50 U0.55 U0.56 U0.57 U0.58 U0.59 U0.61 U0.62 U4.7 U4.8 U4.9 U4.10 U6.2 U6.3 U6.5 USB_H.VSS USB_H.VSS2 Y0.
copper on no net:
  other v1: 56.134,-30.861 55.118,-30.607
  other v2: 4.102,-56.991 4.102,-52.991

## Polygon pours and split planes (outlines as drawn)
GND on Top Layer "Top Layer-No Net" (solid): 0.254,2.921 88,2.921 88,-66.686 87.63,-67.056 87.607,-67.079 0,-67.079
GND on Bottom Layer "Top Layer-No Net" (solid): 0,2.921 88,2.921 88,-67.056 0.254,-67.056

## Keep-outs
Keep-Out Layer:
  lines w0.254: 0,-67.079 0,2.921 88,2.921 88,-67.056 0,-67.056

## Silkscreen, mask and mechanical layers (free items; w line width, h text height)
Top Overlay:
  drawing of 493 lines, arcs and shapes, not listed
  text "13688670331 v0.01" at 52.705,-62.738 h1.52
